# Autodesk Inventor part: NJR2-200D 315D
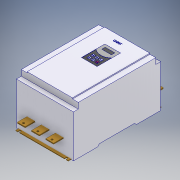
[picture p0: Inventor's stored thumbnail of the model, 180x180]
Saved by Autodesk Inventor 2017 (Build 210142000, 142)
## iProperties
Part Number: NJR2-200D 315D
Material: Типовые
Document SubType Name: Modeling
Designer: RSagdiev
Density: 1 g/cm^3
Appearance: По умолчанию
Author: RSagdiev
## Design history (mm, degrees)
sketch "Эскиз1"
  geometry: L1 (0, 0)-(15.898, 0) reference; L2 (0, 0)-(0, 16.101) reference; L3 (0, 0)-(124, 0); L4 (448, 0)-(448, 218); L5 (134, -10)-(314, -10); L6 (314, -10)-(314, 0); L7 (314, 10)-(134, 10); L8 (134, 10)-(134, 10); L9 (134, -10)-(314, 10); L10 (314, -10)-(134, 10); L11 (324, 0)-(448, 0); L12 (134, 0)-(224, 0); L13 (224, 0)-(314, 0); L14 (314, 10)-(314, 10); L15 (134, 0)-(134, -10); L16 (314, 10)-(324, 0); L17 (134, 10)-(124, 0); L18 (423, 253)-(423, 218); L19 (423, 218)-(448, 218); L20 (25, 253)-(25, 218); L21 (25, 218)-(0, 218); L22 (0, 218)-(0, 0); L23 (423, 253)-(25, 253); 1 further point
  constraints: 46 end point, 10 parallel, 10 perpendicular, 7 horizontal, 4 midpoint, 4 point on line, 2 vertical, 1 other
  dimensions: "d2" = 180 distance of L7.end L7.start; "d3" = 20 distance of L7.start L5.end; "d4" = 224 distance from line of L12.end L4 (= 0.5 x d158); "d5" = 10 distance of L14.start L6.end; "d6" = 10 distance of L11.start L6.end (= d5); "d7" = 10 distance of L8.end L12.start (= d5); "d8" = 10 distance of L3.end L12.start (= d7); "d10" = 35 distance of L18.end L18.start; "d11" = 25 distance of L20.end L21.end; "d12" = 35 distance of L20.start L20.end; "d157" = 253 distance between parallel lines of L23 L11; "d158" = 448 distance between parallel lines of L22 L4; "d159" = 25 horizontal distance of L4.end L18.start
extrude "Выдавливание1" new body sketch "Эскиз1" stored distance "d13" = 293; taper "d14" = 0 deg
sketch "Эскиз2"
  geometry: L1 (0, 0)-(293, 0); L2 (293, 398)-(293, 0); L3 (293, 398)-(0, 398); L4 (0, 0)-(0, 398); L5 (0, 0)-(0, 398); L6 (0, 0)-(293, 0); L7 (0, 398)-(30, 398); L8 (30, 398)-(30, 0); L9 (30, 0)-(0, 0); L10 (0, 0)-(0, 398); L11 (293, 398)-(263, 398); L12 (263, 398)-(263, 0); L13 (263, 0)-(293, 0); L14 (293, 0)-(293, 398); L15 (293, 398)-(0, 398) reference; L16 (293, 398)-(293, 0) reference; L17 (0, 0)-(0, 398) reference; L18 (293, 0)-(0, 0) reference; 1 further point
  constraints: 28 end point, 4 collinear, 4 parallel, 2 horizontal, 2 perpendicular, 2 point on line
  dimensions: "d15" = 30 distance of L8.end L9.end; "d16" = 30 distance of L13.end L12.end
extrude "Выдавливание2" cut sketch "Эскиз2" distance "d17" = 5; taper "d18" = 0 deg
sketch "Эскиз3"
  geometry: L1 (463, 3.5)-(363, 3.5); L2 (363, 3.5)-(363, 0.5); L3 (363, 0.5)-(463, 0.5); L4 (463, 0.5)-(463, 3.5); L5 (85, 3.5)-(85, 0.5); L6 (-15, 3.5)-(85, 3.5); L7 (-15, 0.5)-(-15, 3.5); L8 (85, 0.5)-(-15, 0.5); L9 (25, 253)-(423, 253) reference; L10 (134, 10)-(314, 10) reference; L11 (324, 0)-(448, 0) reference; L12 (0, 218)-(0, 0) reference; L13 (448, 0)-(448, 218) reference; L14 (224, 34.1)-(224, 218)
  constraints: 18 end point, 2 parallel, 1 collinear, 1 horizontal, 1 perpendicular, 1 vertical
  dimensions: "d20" = 3 distance of L2.end L1.end; "d24" = 478 distance between parallel lines of L7 L4; "d166" = 3 distance between parallel lines of L6 L8; "d167" = 0.5 distance between parallel lines of L3 L11; "d168" = 100 distance of L5.end L7.start (derived); "d169" = 448 distance between parallel lines of L12 L13 (derived); "d170" = 224 distance between parallel lines of L14 L13 (= 0.5 x d169); "d171" = 139 distance between parallel lines of L2 L14; "d172" = 139 distance between parallel lines of L5 L14 (= d171); "d173" = 15 distance between parallel lines of L4 L13 (= -0.5 x d169 + 0.5 x d24)
extrude "Выдавливание3" new body sketch "Эскиз3" stored distance "d25" = 270; taper "d26" = 0 deg
sketch "Эскиз4"
  geometry: L1 (270, 0)-(0, 0) reference; L2 (0, -100)-(0, 0) reference; L3 (270, -100)-(0, -100) reference; L4 (270, 0)-(270, -100) reference; L5 (270, 0)-(0, 0) reference; L6 (135, 0)-(135, -100); L7 (270, -100)-(0, -100) reference; L8 (270, -378)-(0, -378) reference; L9 (0, -478)-(0, -378) reference; L10 (270, -478)-(0, -478) reference; L11 (270, -378)-(270, -478) reference; L12 (15, -470.5)-(15, -478); L13 (10.5, -470.5)-(10.5, -478); L14 (19.5, -478)-(19.5, -470.5); L15 (255, -470.5)-(255, -478); L16 (250.5, -470.5)-(250.5, -478); L17 (259.5, -478)-(259.5, -470.5); C1 r 4.5 at (15, -6.5); C2 r 4.5 at (255, -6.5); A1 r 4.5 centre (15, -470.5) between (19.5, -470.5) and (10.5, -470.5); A2 r 4.5 centre (15, -478) between (10.5, -478) and (19.5, -478); A3 r 4.5 centre (255, -470.5) between (259.5, -470.5) and (250.5, -470.5); A4 r 4.5 centre (255, -478) between (250.5, -478) and (259.5, -478); 3 further points
  constraints: 18 end point, 8 point on circle, 8 tangent, 6 centre point, 4 midpoint, 2 parallel, 2 perpendicular, 2 point on line
  dimensions: "d27" = 9 diameter of C1; "d28" = 9 diameter of C2 (= d27); "d29" = 240 distance of C2.centre C1.centre; "d31" = 120 distance from line of C1.centre L6 (= 0.5 x d29); "d32" = 120 distance from line of L6 C2.centre (= d31); "d33" = 6.5 distance from line of L1 C1.centre (computed from d27); "d34" = 6.5 distance from line of L1 C2.centre (derived); "d35" = 9 diameter of A2 (= d27); "d36" = 7.5 distance from line of L10 L12.start (computed from d35); "d37" = 9 diameter of A4 (= d35); "d38" = 7.5 distance from line of L10 L15.start (= d36); "d39" = 240 distance of L15.start L12.start (= d29); "d40" = 120 horizontal distance of point (135, -463) L12.start (= d31); "d41" = 120 horizontal distance of point (135, -463) L15.start (derived); "d181" = 464 distance of L12.start C1.centre (derived)
extrude "Выдавливание4" cut sketch "Эскиз4" stored distance "d42" = 240; taper "d43" = 0 deg
node "РабПлоскость1"
sketch "Эскиз5" dims "d50" = 293 (derived), "d56" = 10, "d67" = 10
  geometry: L1 (43.5, 135.5)-(83.5, 135.5); L2 (83.5, 135.5)-(83.5, -413.5); L3 (83.5, -413.5)-(43.5, -413.5); L4 (43.5, -413.5)-(43.5, 135.5); L5 (281.5, 85)-(-11.5, 85) reference; L6 (-11.5, -139)-(281.5, -139); L7 (116.75, 135.5)-(156.75, 135.5); L8 (156.75, 135.5)-(156.75, -413.5); L9 (156.75, -413.5)-(116.75, -413.5); L10 (116.75, -413.5)-(116.75, 135.5); L11 (190, 135.5)-(230, 135.5); L12 (230, 135.5)-(230, -413.5); L13 (230, -413.5)-(190, -413.5); L14 (190, -413.5)-(190, 135.5); L15 (281.5, -363)-(-11.5, -363) reference; C1 r 5 at (63.5, 123.5); C2 r 5 at (136.75, 123.5); C3 r 5 at (210, 123.5); C4 r 5 at (136.75, -401.5); C5 r 5 at (210, -401.5); C6 r 5 at (63.5, -401.5); 9 further points; 2 other entities
  constraints: 26 end point, 6 centre point, 3 horizontal, 3 symmetric about line, 2 parallel, 1 perpendicular, 27 other
  dimensions: "d45" = 549 distance between parallel lines of L3 L1; "d46" = 40 distance between parallel lines of L2 L4; "d49" = 55 dimension on L4; "d53" = 73.25 distance of L1.start L7.start (= 0.25 x d50); "d59" = 10 diameter of C1; "d60" = 20 distance from line of C1.centre L4; "d61" = 12 distance from line of C1.centre L1; "d64" = 73.25 distance of C1.centre C2.centre (= d53); "d177" = 448 distance between parallel lines of L15 L5 (derived); "d178" = 50.5 distance between parallel lines of L1 L5 (= -0.5 x d177 + 0.5 x d45); "d179" = 224 distance between parallel lines of L5 L6 (derived); "d180" = 224 distance between parallel lines of L15 L6 (derived)
extrude "Выдавливание5" new body sketch "Эскиз5" distance "d69" = 5; taper "d70" = 0 deg
node "РабПлоскость2"
sketch "Эскиз6" dims "d79" = 10, "d89" = 10
  geometry: L1 (83.5, 135.5)-(43.5, 135.5) reference; L2 (43.5, 135.5)-(43.5, -413.5) reference; L3 (43.5, -413.5)-(83.5, -413.5) reference; L4 (83.5, -413.5)-(83.5, 135.5) reference; L5 (156.75, 135.5)-(116.75, 135.5) reference; L6 (116.75, 135.5)-(116.75, -413.5) reference; L7 (116.75, -413.5)-(156.75, -413.5) reference; L8 (156.75, -413.5)-(156.75, 135.5) reference; L9 (230, 135.5)-(190, 135.5) reference; L10 (190, 135.5)-(190, -413.5) reference; L11 (190, -413.5)-(230, -413.5) reference; L12 (230, -413.5)-(230, 135.5) reference; L13 (-11.5, -139)-(281.5, -139) reference; L14 (281.5, -39)-(-11.5, -39) reference; L15 (43.5, -39)-(83.5, -39); L16 (83.5, -39)-(83.5, 150.5); L17 (83.5, 150.5)-(43.5, 150.5); L18 (43.5, 150.5)-(43.5, -39); L19 (116.75, -39)-(156.75, -39); L20 (156.75, -39)-(156.75, 150.5); L21 (116.75, 150.5)-(116.75, -39); L22 (156.75, 150.5)-(116.75, 150.5); L23 (190, -39)-(230, -39); L24 (230, -39)-(230, 150.5); L25 (190, 150.5)-(190, -39); L26 (230, 150.5)-(190, 150.5); C1 r 5 at (63.5, -401.5) reference; C2 r 5 at (63.5, 123.5) reference; C3 r 5 at (136.75, -401.5) reference; C4 r 5 at (136.75, 123.5) reference; C5 r 5 at (210, -401.5) reference; C6 r 5 at (210, 123.5) reference; C7 r 5 at (63.5, 138.5); C8 r 5 at (136.75, 138.5); C9 r 5 at (210, 138.5); 8 further points
  constraints: 24 end point, 3 centre point, 3 horizontal, 2 parallel, 2 point on line, 1 collinear, 1 perpendicular, 27 other
  dimensions: "d72" = 40 distance between parallel lines of L16 L18 (= d46); "d73" = 15 distance between parallel lines of L17 L1; "d76" = 73.25 distance of L1.start point (156.75, 135.5) (= d53); "d81" = 10 diameter of C7; "d82" = 12 distance from line of L17 C7.centre (= d61); "d83" = 20 distance from line of L18 C7.centre (= d60); "d86" = 73.25 distance of C7.centre C8.centre (= d53)
extrude "Выдавливание6" new body sketch "Эскиз6" distance "d91" = 5; taper "d92" = 0 deg
sketch "Эскиз7"
  geometry: L1 (233, -398)-(233, 0); L2 (233, 0)-(0, 0); L3 (0, 0)-(0, -398); L4 (0, -398)-(233, -398); L5 (156.5, -195)-(76.5, -195); L6 (76.5, -195)-(76.5, -119.989); L7 (76.5, -75)-(156.5, -75); L8 (156.5, -75)-(156.5, -119.721); L9 (156.5, -195)-(76.5, -75); L10 (76.5, -195)-(156.5, -75); L11 (156.7, -74.8)-(76.3, -74.8); L12 (76.3, -74.8)-(76.3, -195.2); L13 (76.3, -195.2)-(156.7, -195.2); L14 (156.7, -195.2)-(156.7, -74.8); L15 (156.5, -119.721)-(156.5, -119.989); L16 (156.5, -119.989)-(156.5, -195); L17 (76.5, -119.721)-(76.5, -75); L18 (76.5, -119.989)-(76.5, -119.721); L19 (92.5, -88.361)-(140.5, -88.361); L20 (141.5, -89.361)-(141.5, -105.361); L21 (140.5, -106.361)-(92.5, -106.361); L22 (91.5, -105.361)-(91.5, -89.361); L23 (91.5, -88.361)-(141.5, -106.361); L24 (141.5, -88.361)-(91.5, -106.361); L25 (116.5, -135)-(116.5, -195.2); L26 (96.5, -131.781)-(96.5, -195); L27 (136.5, -131.781)-(136.5, -195); L28 (76.5, -175)-(156.5, -175); L29 (76.5, -155)-(156.5, -155); L30 (90.5, -149)-(102.5, -149); L31 (102.5, -149)-(102.5, -161); L32 (102.5, -161)-(90.5, -161); L33 (90.5, -161)-(90.5, -149); L34 (90.5, -149)-(102.5, -161); L35 (102.5, -149)-(90.5, -161); L36 (90.5, -169)-(102.5, -169); L37 (102.5, -169)-(102.5, -181); L38 (102.5, -181)-(90.5, -181); L39 (90.5, -181)-(90.5, -169); L40 (90.5, -169)-(102.5, -181); L41 (102.5, -169)-(90.5, -181); L42 (130.5, -149)-(142.5, -149); L43 (142.5, -149)-(142.5, -161); L44 (142.5, -161)-(130.5, -161); L45 (130.5, -161)-(130.5, -149); L46 (130.5, -149)-(142.5, -161); L47 (142.5, -149)-(130.5, -161); L48 (130.5, -169)-(142.5, -169); L49 (142.5, -169)-(142.5, -181); L50 (142.5, -181)-(130.5, -181); L51 (130.5, -181)-(130.5, -169); L52 (130.5, -169)-(142.5, -181); L53 (142.5, -169)-(130.5, -181); L54 (110.5, -149)-(122.5, -149); L55 (122.5, -149)-(122.5, -161); L56 (122.5, -161)-(110.5, -161); L57 (110.5, -161)-(110.5, -149); L58 (110.5, -149)-(122.5, -161); L59 (122.5, -149)-(110.5, -161); L60 (110.5, -169)-(122.5, -169); L61 (122.5, -169)-(122.5, -181); L62 (122.5, -181)-(110.5, -181); L63 (110.5, -181)-(110.5, -169); L64 (110.5, -169)-(122.5, -181)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; A1 r 60 centre (116.5, -75) between (76.5, -119.721) and (156.5, -119.721); A2 r 60.2 centre (116.5, -75) between (76.5, -119.989) and (156.5, -119.989); A3 r 1 centre (92.5, -89.361) between (92.5, -88.361) and (91.5, -89.361); A4 r 1 centre (92.5, -105.361) between (91.5, -105.361) and (92.5, -106.361); A5 r 1 centre (140.5, -105.361) between (140.5, -106.361) and (141.5, -105.361); A6 r 1 centre (140.5, -89.361) between (141.5, -89.361) and (140.5, -88.361); 8 further points
  constraints: 130 end point, 26 parallel, 23 point on line, 20 midpoint, 14 point on circle, 13 perpendicular, 8 horizontal, 8 tangent, 6 centre point, 3 equal radius, 2 collinear, 1 vertical
  dimensions: "d93" = 80 distance of L7.start L7.end; "d94" = 120 distance of L5.end L7.start; "d95" = 75 distance between parallel lines of L2 L7; "d96" = 76.5 distance between parallel lines of L3 L6 (= -0.5 x d93 + 0.5 x d174); "d97" = 0.2 distance between parallel lines of L7 L11; "d98" = 60 radius of A1; "d99" = 0.2 radial gap between concentric circles of A1 A2; "d100" = 0.2 distance between parallel lines of L6 L12; "d101" = 0.2 distance between parallel lines of L16 L14; "d102" = 0.2 distance between parallel lines of L5 L13; "d103" = 50 distance of L23.end L24.end; "d104" = 18 distance of L24.start L23.end; "d105" = 1 radius of A3; "d106" = 13.36068 distance between parallel lines of L7 L19; "d107" = 15 distance between parallel lines of L17 L22; "d108" = 20 distance between parallel lines of L25 L26 (= 0.25 x d93); "d109" = 20 horizontal distance of L25.end L27.end (= d108); "d110" = 20 distance between parallel lines of L5 L28 (= d108); "d111" = 20 distance between parallel lines of L28 L29 (= d108); "d112" = 12 distance of L31.end L32.end; "d113" = 12 distance of L30.end L31.end; "d114" = 12 distance of L37.end L38.end; "d115" = 12 distance of L36.end L37.end; "d116" = 12 distance of L43.end L44.end; "d117" = 12 distance of L42.end L43.end; "d118" = 12 distance of L49.end L50.end; "d119" = 12 distance of L48.end L49.end; "d120" = 12 distance of L55.end L56.end; "d121" = 12 distance of L54.end L55.end; "d122" = 12 distance of L61.end L62.end; "d123" = 12 distance of L60.end L61.end; "d174" = 233 distance of L3.end L1.start
extrude "Выдавливание7" cut sketch "Эскиз7" distance "d124" = 10; taper "d125" = 0 deg
extrude "Выдавливание8" cut sketch "Эскиз7" distance "d126" = 1; taper "d127" = 0 deg
extrude "Выдавливание9" cut sketch "Эскиз7" distance "d128" = 0.1; taper "d129" = 0 deg
sketch "Эскиз8" dims "d139" = 7, "d140" = 7
  geometry: L1 (0, 12)-(0, 0); L2 (1, 4)-(10.784, 4); L3 (0, 0)-(12, 0); L4 (43, 4)-(49.667, 4); L5 (3, -16)-(9.899, -16); L6 (42, -16)-(49.667, -16); L7 (0, -8)-(0, -20); L8 (40, 12)-(40, 0); L9 (40, -8)-(40, -20); L10 (40, 0)-(52, 0); L11 (40, -20)-(52, -20); L12 (0, -20)-(12, -20); L13 (20, 12)-(20, 0); L14 (20, 0)-(32, 0); L15 (32, 0)-(32, 12); L16 (32, 12)-(20, 12); L17 (20, -8)-(20, -20); L18 (20, -20)-(32, -20); L19 (32, -20)-(32, -8); L20 (32, -8)-(20, -8); L21 (20, 12)-(32, 0); L22 (32, 0)-(32, 12); L23 (32, 12)-(20, 0); L24 (32, -8)-(20, -8); L25 (20, -8)-(32, -20); L26 (32, -8)-(20, -20); L27 (26, 9.5)-(29.031, 4.25); L28 (29.031, 4.25)-(22.969, 4.25); L29 (22.969, 4.25)-(26, 9.5); L30 (26, -17.5)-(22.969, -12.25); L31 (22.969, -12.25)-(29.031, -12.25); L32 (29.031, -12.25)-(26, -17.5); 5 further points
  constraints: 64 end point, 8 horizontal, 2 coincident, 2 midpoint, 2 perpendicular, 2 vertical alignment, 18 other
  dimensions: "d130" = 1 distance from line of L1 L2.start; "d131" = 4 distance between parallel lines of L3 L2; "d133" = 3 distance from line of L7 L5.start; "d134" = 3 distance from line of L8 L4.start; "d135" = 2 distance from line of L9 L6.start; "d136" = 4 distance between parallel lines of L10 L4 (= d131); "d137" = 4 distance between parallel lines of L11 L6 (= d131); "d138" = 4 distance between parallel lines of L12 L5 (= d131)
feature "Рельеф1" dims "d2" = 180, "d3" = 20, "d4" = 224 (= 0.5 x d158), "d5" = 10, "d6" = 10 (= d5), "d7" = 10 (= d5), "d8" = 10 (= d7), "d10" = 35, "d11" = 25, "d12" = 35, "d141" = 0.1, "d142" = 0, "d157" = 253, "d158" = 448, "d159" = 25
feature "Рельеф2" dims "d2" = 180, "d3" = 20, "d4" = 224 (= 0.5 x d158), "d5" = 10, "d6" = 10 (= d5), "d7" = 10 (= d5), "d8" = 10 (= d7), "d10" = 35, "d11" = 25, "d12" = 35, "d143" = 0.1, "d144" = 0, "d157" = 253, "d158" = 448, "d159" = 25
feature "Рельеф3" dims "d2" = 180, "d3" = 20, "d4" = 224 (= 0.5 x d158), "d5" = 10, "d6" = 10 (= d5), "d7" = 10 (= d5), "d8" = 10 (= d7), "d10" = 35, "d11" = 25, "d12" = 35, "d145" = 0.1, "d146" = 0, "d157" = 253, "d158" = 448, "d159" = 25
feature "Рельеф4" dims "d2" = 180, "d3" = 20, "d4" = 224 (= 0.5 x d158), "d5" = 10, "d6" = 10 (= d5), "d7" = 10 (= d5), "d8" = 10 (= d7), "d10" = 35, "d11" = 25, "d12" = 35, "d147" = 0.1, "d148" = 0, "d157" = 253, "d158" = 448, "d159" = 25
feature "Рельеф5" dims "d2" = 180, "d3" = 20, "d4" = 224 (= 0.5 x d158), "d5" = 10, "d6" = 10 (= d5), "d7" = 10 (= d5), "d8" = 10 (= d7), "d10" = 35, "d11" = 25, "d12" = 35, "d149" = 0.1, "d150" = 0, "d157" = 253, "d158" = 448, "d159" = 25
feature "Рельеф6" dims "d2" = 180, "d3" = 20, "d4" = 224 (= 0.5 x d158), "d5" = 10, "d6" = 10 (= d5), "d7" = 10 (= d5), "d8" = 10 (= d7), "d10" = 35, "d11" = 25, "d12" = 35, "d151" = 0.1, "d152" = 0, "d157" = 253, "d158" = 448, "d159" = 25
sketch "Эскиз9"
  geometry: L1 (81.5, -40)-(127.615, -40); L2 (76.5, -195.2)-(76.5, -74.8); L3 (-30, 0)-(223, 0); L4 (76.5, -75)-(76.5, -119.989) reference; 1 further point
  constraints: 6 end point, 2 horizontal, 1 collinear
  dimensions: "d153" = 5 distance from line of L2 L1.start; "d154" = 40 distance between parallel lines of L3 L1
feature "Рельеф7" sketch "Эскиз9" dims "d2" = 180, "d3" = 20, "d4" = 224 (= 0.5 x d158), "d5" = 10, "d6" = 10 (= d5), "d7" = 10 (= d5), "d8" = 10 (= d7), "d10" = 35, "d11" = 25, "d12" = 35, "d155" = 0.1, "d156" = 0, "d157" = 253, "d158" = 448, "d159" = 25
node "Твердое тело1"
node "Твердое тело2"
node "Спроецированная петля3"
node "Спроецированная петля4"
node "Твердое тело3"
node "Спроецированная петля5"
node "Спроецированная петля6"
node "Спроецированная петля7"
node "Твердое тело4"
other parameters: "d71" = -35
